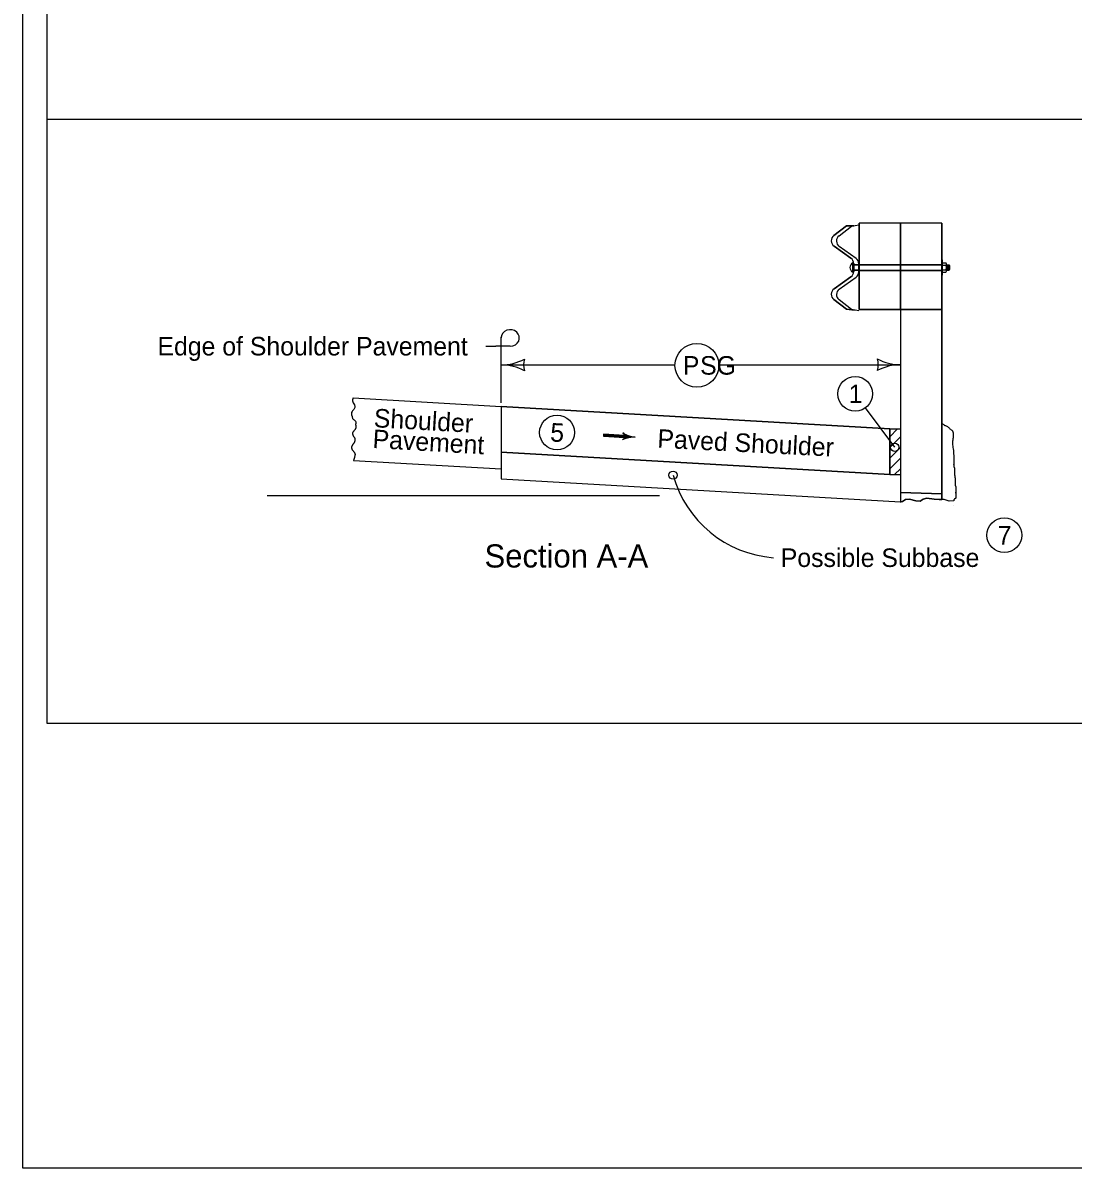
# Model space of a CAD drawing. Extents: x 6410 to 81668, y 3928 to 11667.
# Drawn here: x 10133 to 11038, y 7924 to 8912 of the extents above; entities that cross this region are included whole.
import ezdxf

# ---------------------------------------------------------------- set-up
doc = ezdxf.new("R2010")
doc.units = 0
for name, color, linetype in [('dsnCellElements', 7, 'Continuous'), ('dsnNonPlotable', 7, 'Continuous'), ('dsnShtPlotShapeBatchPrint', 7, 'Continuous'), ('dsnStdBlockModified', 7, 'Continuous'), ('Level 11', 7, 'Continuous'), ('Level 14', 7, 'Continuous'), ('Level 3', 7, 'Continuous'), ('Level 7', 7, 'Continuous'), ('Level 8', 7, 'Continuous')]:
    doc.layers.add(name, color=color, linetype=linetype)

msp = doc.modelspace()

# ---------------------------------------------------------------- linework, layer by layer
at = {"layer": 'dsnCellElements'}
for p, q in [((10545.11, 8620.44), (10545.11, 8641.3)), ((10531.74, 8633.28), (10540.43, 8633.28)), ((10552.92, 8633.28), (10540.43, 8633.28)), ((10545.11, 8584.5), (10545.11, 8620.44)), ((10651.5, 8555.4), (10633.29, 8556.45)), ((10651.39, 8554.46), (10651.39, 8554.46)), ((10651.51, 8556.4), (10651.51, 8556.4))]:
    msp.add_line(p, q, dxfattribs=at)
for points in [[(10651.52, 8556.34), (10633.36, 8557.39), (10633.23, 8555.51), (10651.39, 8554.46), (10651.45, 8556.07), (10633.58, 8557.16), (10633.52, 8555.67), (10651.01, 8554.72), (10651.13, 8555.84), (10633.81, 8556.9), (10633.79, 8555.9), (10650.8, 8554.92), (10650.89, 8555.62), (10634, 8556.68), (10633.98, 8556.12), (10650.59, 8555.18)], [(10651.12, 8557.59), (10651.81, 8556.43), (10651.79, 8554.78), (10651.03, 8553.38), (10653.79, 8554.25), (10656.98, 8554.9), (10657.88, 8555.03), (10655.64, 8555.58), (10652.41, 8556.81), (10651.47, 8557.34), (10651.59, 8553.83), (10656.54, 8555.05), (10651.9, 8556.63), (10651.91, 8554.21), (10655.31, 8555.14), (10652.31, 8556), (10652.08, 8554.62), (10654.24, 8555.12), (10652.65, 8555.63), (10652.51, 8554.97), (10653.3, 8555.13)]]:
    msp.add_lwpolyline(points, dxfattribs=at)
for centre, major_axis, start_param, end_param in [((10552.92, 8640.42), (-7.81, 0), 1.570796, 6.283185), ((10647.73, 8555.61), (3.88, 0), 5.202895, 7.237436), ((10662.79, 8575.03), (-22.17, 0), 0.954258, 1.478381), ((10660, 8534.61), (22.17, 0), 1.537172, 2.061295)]:
    msp.add_ellipse(centre, major_axis=major_axis, ratio=0.913811, start_param=start_param, end_param=end_param, dxfattribs=at)
at = {"layer": 'dsnNonPlotable'}
for p, q in [((10153.18, 9917.9), (10153.18, 8307.9)), ((10153.18, 8307.9), (13248.87, 8307.9))]:
    msp.add_line(p, q, dxfattribs=at)
at = {"layer": 'dsnShtPlotShapeBatchPrint'}
for p, q in [((10545.11, 8617.12), (10694.94, 8617.12)), ((10732.8, 8617.27), (10889.5, 8617.27))]:
    msp.add_line(p, q, dxfattribs=at)
msp.add_circle((10713.87, 8616.71), 18.93, dxfattribs=at)
for centre, radius, start, end in [((10545.11, 8659.62), 42.5, 270, 298.07249), ((10580.75, 8617.12), 16.42, 162.26665, 197.73335), ((10853.87, 8617.27), 16.42, 342.26665, 17.73335), ((10889.5, 8659.77), 42.5, 241.92751, 270), ((10545.11, 8574.62), 42.5, 61.92751, 90), ((10889.5, 8574.77), 42.5, 90, 118.07249), ((10787.43, 8548.23), 97.76, 195.59781, 265.55799)]:
    msp.add_arc(centre, radius, start, end, dxfattribs=at)
at = {"layer": 'dsnStdBlockModified'}
for p, q in [((10832.02, 8728.72), (10842.78, 8737.12)), ((10836.45, 8728.49), (10847.23, 8736.9)), ((10842.78, 8737.12), (10849.11, 8737.23)), ((10847.23, 8736.9), (10853.56, 8738.02)), ((10925.05, 8739.48), (10853.96, 8739.48)), ((10853.96, 8664.83), (10853.96, 8739.48)), ((10889.5, 8664.83), (10889.5, 8739.48)), ((10925.05, 8739.48), (10925.05, 8500.84)), ((10846.72, 8709.19), (10832.21, 8719.6)), ((10851.19, 8708.95), (10836.63, 8719.4)), ((10925.05, 8707.78), (10925.73, 8707.78)), ((10925.73, 8694.45), (10925.73, 8707.78)), ((10848.34, 8697.08), (10848.34, 8705.17)), ((10848.34, 8703.48), (10853.77, 8703.48)), ((10848.34, 8698.81), (10853.96, 8698.81)), ((10849.12, 8697.75), (10849.11, 8704.56)), ((10849.11, 8697.74), (10849.12, 8701.15)), ((10849.12, 8701.15), (10849.12, 8697.75)), ((10849.29, 8703.48), (10853.96, 8703.48)), ((10853.56, 8700.93), (10853.56, 8704.34)), ((10853.56, 8697.53), (10853.56, 8700.93)), ((10853.56, 8700.93), (10853.56, 8697.53)), ((10853.95, 8698.48), (10925.05, 8698.48)), ((10853.96, 8703.81), (10925.05, 8703.81)), ((10853.96, 8703.48), (10925.05, 8703.47)), ((10853.96, 8698.81), (10925.05, 8698.81)), ((10925.73, 8705.15), (10928.7, 8705.15)), ((10925.73, 8703.13), (10928.7, 8703.13)), ((10925.73, 8699.09), (10928.7, 8699.09)), ((10925.73, 8697.07), (10928.7, 8697.07)), ((10929.06, 8698.08), (10929.06, 8704.14)), ((10929.06, 8703.45), (10931.43, 8703.45)), ((10929.06, 8698.78), (10931.43, 8698.78)), ((10929.95, 8703.45), (10929.95, 8698.78)), ((10930.69, 8703.45), (10930.69, 8698.78)), ((10931.43, 8703.45), (10931.88, 8702.91)), ((10931.43, 8703.45), (10931.43, 8698.78)), ((10931.88, 8699.31), (10931.43, 8698.78)), ((10931.88, 8702.91), (10931.88, 8699.31)), ((10832.21, 8682.7), (10846.72, 8693.11)), ((10836.63, 8682.46), (10851.19, 8692.91)), ((10925.05, 8694.45), (10925.73, 8694.45)), ((10842.78, 8665.18), (10832.02, 8673.58)), ((10847.23, 8664.96), (10836.45, 8673.37)), ((10849.88, 8664.49), (10842.78, 8665.18)), ((10853.56, 8663.85), (10847.23, 8664.96)), ((10889.5, 8664.83), (10853.96, 8664.83)), ((10889.5, 8664.83), (10889.5, 8498.31)), ((10417.5, 8588.78), (10545.11, 8581.36)), ((10545.11, 8581.36), (10545.11, 8527.35)), ((10545.11, 8581.36), (10880.25, 8561.87)), ((10880.25, 8561.87), (10545.11, 8581.36)), ((10545.11, 8581.36), (10545.11, 8541.76)), ((10880.25, 8555.12), (10886.99, 8561.87)), ((10880.25, 8555.12), (10886.99, 8561.87)), ((10880.25, 8555.12), (10886.99, 8561.87)), ((10880.25, 8555.12), (10886.99, 8561.87)), ((10880.25, 8561.87), (10889.49, 8561.87)), ((10880.25, 8561.87), (10880.25, 8522.44)), ((10880.25, 8522.44), (10880.25, 8561.87)), ((10880.25, 8545.94), (10889.49, 8555.18)), ((10880.25, 8545.94), (10889.49, 8555.18)), ((10880.25, 8545.94), (10889.49, 8555.18)), ((10880.25, 8545.94), (10889.49, 8555.18)), ((10935.1, 8555.1), (10935.1, 8555.1)), ((10880.25, 8522.44), (10545.11, 8541.76)), ((10545.11, 8541.76), (10880.25, 8522.44)), ((10880.25, 8536.71), (10889.49, 8545.95)), ((10880.25, 8536.71), (10889.49, 8545.95)), ((10880.25, 8536.71), (10889.49, 8545.95)), ((10880.25, 8536.71), (10889.49, 8545.95)), ((10417.68, 8534.76), (10545.11, 8527.35)), ((10880.25, 8527.48), (10889.49, 8536.72)), ((10545.11, 8527.35), (10545.11, 8518.93)), ((10545.11, 8518.93), (10889.5, 8499.07)), ((10880.25, 8522.44), (10889.49, 8522.44)), ((10884.35, 8522.44), (10889.49, 8527.58)), ((10343.06, 8504.51), (10681.56, 8504.51)), ((10935.45, 8496.03), (10935.45, 8496.03))]:
    msp.add_line(p, q, dxfattribs=at)
for points in [[(10929.05, 8698.41), (10929, 8698.67), (10928.96, 8698.85), (10928.87, 8699), (10928.75, 8699.09), (10928.83, 8699.19), (10928.91, 8699.42), (10928.97, 8699.73), (10929.05, 8700.48), (10929.05, 8698.4), (10929.03, 8698.55), (10928.99, 8698.76), (10928.91, 8698.97), (10928.79, 8699.08), (10928.83, 8699.17), (10928.89, 8699.32), (10928.99, 8699.82), (10929.03, 8700.2), (10929.03, 8698.6), (10929, 8698.72), (10928.96, 8698.88), (10928.83, 8699.08), (10928.88, 8699.25), (10928.96, 8699.59), (10929.02, 8699.91), (10929.01, 8698.75), (10928.97, 8698.88), (10928.86, 8699.07), (10928.9, 8699.29), (10928.96, 8699.55), (10928.99, 8699.72), (10928.99, 8698.86), (10928.93, 8698.96), (10928.88, 8699.08), (10928.97, 8699.54), (10928.97, 8698.94), (10928.9, 8699.07), (10928.95, 8699.37), (10928.95, 8699.01), (10928.92, 8699.08), (10928.93, 8699.18), (10928.93, 8699.11)], [(10928.76, 8703.14), (10928.83, 8703.18), (10928.91, 8703.28), (10928.99, 8703.5), (10929.05, 8703.79), (10929.05, 8701.84), (10928.99, 8702.36), (10928.94, 8702.73), (10928.82, 8703.05), (10928.76, 8703.13), (10928.82, 8703.14), (10928.92, 8703.29), (10929.01, 8703.52), (10929.03, 8703.67), (10929.03, 8702.13), (10928.96, 8702.63), (10928.9, 8702.89), (10928.8, 8703.11), (10928.83, 8703.13), (10928.97, 8703.34), (10929.01, 8703.5), (10929.01, 8702.39), (10928.82, 8703.1), (10928.99, 8703.38), (10928.99, 8702.53), (10928.85, 8703.09), (10928.97, 8703.31), (10928.98, 8702.67), (10928.87, 8703.07), (10928.96, 8703.25), (10928.96, 8702.83), (10928.89, 8703.06), (10928.94, 8703.17), (10928.94, 8702.97), (10928.91, 8703.04), (10928.92, 8703.09)], [(10935.57, 8531.26), (10935.51, 8530.99), (10935.51, 8530.79), (10935.51, 8530.6), (10935.51, 8530.4), (10935.51, 8530.21), (10935.51, 8530.01), (10935.51, 8529.72), (10935.51, 8529.52), (10935.61, 8529.23), (10935.71, 8528.94), (10935.9, 8528.74), (10935.9, 8528.55), (10936, 8528.35), (10936, 8528.16), (10936, 8527.96), (10936.1, 8527.86), (10936.1, 8527.67), (10936.1, 8527.47), (10936.1, 8527.28), (10936.1, 8527.08), (10936.1, 8526.89), (10936.1, 8526.59), (10936.1, 8526.3), (10936.1, 8526.1), (10936.1, 8525.81), (10936.1, 8525.62), (10936.1, 8525.42), (10936.2, 8525.32), (10936.2, 8525.13), (10936.2, 8524.93), (10936.2, 8524.74), (10936.2, 8524.54), (10936.2, 8524.34), (10936.2, 8524.15), (10936.2, 8523.95), (10936.2, 8523.76), (10936.2, 8523.56), (10936.2, 8523.37), (10936.2, 8523.17), (10936.2, 8522.98), (10936.2, 8522.78), (10936.2, 8522.59), (10936.2, 8522.39), (10936.2, 8522.2), (10936.2, 8522), (10936.2, 8521.8), (10936.29, 8521.71), (10936.29, 8521.51), (10936.29, 8521.32), (10936.39, 8521.22), (10936.39, 8521.02), (10936.39, 8520.83), (10936.49, 8520.73), (10936.49, 8520.53), (10936.49, 8520.34), (10936.49, 8520.14), (10936.49, 8519.85), (10936.59, 8519.56), (10936.59, 8519.36), (10936.59, 8519.17), (10936.59, 8518.97), (10936.59, 8518.78), (10936.59, 8518.58), (10936.59, 8518.38), (10936.59, 8518.19), (10936.59, 8517.99), (10936.59, 8517.8), (10936.59, 8517.6), (10936.59, 8517.41), (10936.59, 8517.21), (10936.59, 8517.02), (10936.59, 8516.82), (10936.59, 8516.63), (10936.59, 8516.43), (10936.59, 8516.24), (10936.59, 8516.04), (10936.59, 8515.84), (10936.59, 8515.65), (10936.59, 8515.45), (10936.59, 8515.26), (10936.59, 8515.06), (10936.59, 8514.87), (10936.59, 8514.67), (10936.59, 8514.48), (10936.59, 8514.28), (10936.59, 8514.09), (10936.59, 8513.89), (10936.68, 8513.79), (10936.68, 8513.5), (10936.68, 8513.3), (10936.78, 8513.11), (10936.88, 8512.82), (10936.88, 8512.62), (10936.98, 8512.52), (10936.98, 8512.33), (10937.07, 8512.23), (10937.17, 8512.13), (10937.17, 8511.94), (10937.17, 8511.74), (10937.17, 8511.55), (10937.27, 8511.45), (10937.27, 8511.25), (10937.27, 8511.06), (10937.27, 8510.86), (10937.27, 8510.67), (10937.27, 8510.47), (10937.27, 8510.28), (10937.27, 8510.08), (10937.27, 8509.88), (10937.27, 8509.69), (10937.27, 8509.49), (10937.27, 8509.3), (10937.27, 8509.1), (10937.27, 8508.91), (10937.27, 8508.71), (10937.27, 8508.52), (10937.27, 8508.32), (10937.27, 8508.13), (10937.27, 8507.93), (10937.27, 8507.74), (10937.27, 8507.54), (10937.27, 8507.34), (10937.27, 8507.15), (10937.27, 8506.95), (10937.27, 8506.76), (10937.27, 8506.56), (10937.27, 8506.56), (10937.27, 8506.86), (10937.27, 8507.05), (10937.27, 8507.25), (10937.27, 8507.05), (10937.27, 8506.86), (10937.27, 8506.66), (10937.27, 8506.46), (10937.27, 8506.27), (10937.27, 8506.07), (10937.27, 8505.88), (10937.27, 8505.68), (10937.27, 8505.49), (10937.27, 8505.29), (10937.27, 8505.1), (10937.27, 8504.9), (10937.27, 8504.71), (10937.27, 8504.51), (10937.27, 8504.32), (10937.17, 8504.22), (10937.17, 8504.02), (10937.17, 8503.83), (10937.17, 8503.63), (10937.17, 8503.44), (10937.17, 8503.24), (10937.17, 8503.05), (10937.17, 8502.85), (10937.17, 8502.65), (10937.17, 8502.46), (10937.17, 8502.26), (10937.07, 8502.17), (10936.98, 8501.97), (10936.88, 8501.87), (10936.78, 8501.78), (10936.68, 8501.68), (10936.49, 8501.58), (10936.29, 8501.58), (10936.2, 8501.48), (10936.1, 8501.38), (10936, 8501.29), (10935.8, 8501.19), (10935.71, 8501.09), (10935.71, 8500.9), (10935.61, 8500.8), (10935.61, 8500.6), (10935.61, 8500.41), (10935.61, 8500.21), (10935.61, 8500.02), (10935.61, 8499.92), (10935.61, 8500.11)], [(10935.57, 8499.8), (10931.42, 8499.68), (10927.28, 8500.84), (10922.73, 8500.84), (10918.49, 8501.27), (10912.23, 8502.01), (10909.16, 8501.37), (10906.51, 8499.57), (10902.8, 8499.78), (10897.18, 8501.37), (10893.9, 8500.84), (10891.14, 8499.25), (10889.5, 8499.03)]]:
    msp.add_lwpolyline(points, dxfattribs=at)
msp.add_circle((10593.23, 8558.79), 15, dxfattribs=at)
for centre, radius, start, end in [((10835.49, 8724.23), 5.68, 127.75002, 234.69086), ((10839.94, 8724.02), 5.68, 127.75002, 234.69086), ((10843.44, 8704.56), 5.68, 360, 54.69099), ((10847.88, 8704.34), 5.68, 360, 54.69099), ((10850.42, 8701.13), 4.54, 117.20289, 242.8461), ((10843.44, 8697.74), 5.68, 305.30901, 0), ((10847.88, 8697.53), 5.68, 305.30901, 0), ((10835.49, 8678.07), 5.68, 125.30914, 232.24998), ((10839.94, 8677.85), 5.68, 125.30914, 232.24998)]:
    msp.add_arc(centre, radius, start, end, dxfattribs=at)
for centre in [(10928.7, 8704.14), (10928.7, 8698.08)]:
    msp.add_ellipse(centre, major_axis=(0, -1.01), ratio=0.362258, start_param=6.283156, end_param=9.424748, dxfattribs=at)
for points in [[(10417.5, 8588.78), (10416.99, 8585.18), (10418.03, 8583.67), (10418.9, 8581.37), (10418.29, 8579.31), (10416.39, 8576.94), (10415.87, 8575.04), (10416.39, 8572.74), (10417.25, 8570.37), (10418.29, 8569.65), (10419.68, 8567.12), (10419.67, 8566.28)], [(10417.71, 8549.17), (10417.92, 8549.41), (10418.12, 8549.68), (10418.47, 8550.23), (10418.75, 8550.83), (10418.87, 8551.13), (10418.97, 8551.45), (10419.1, 8552.07), (10419.15, 8552.69), (10419.1, 8553.27), (10419.04, 8553.55), (10419, 8553.69), (10418.96, 8553.82), (10418.75, 8554.19), (10418.47, 8554.56), (10418.17, 8554.92), (10417.92, 8555.32), (10417.78, 8555.61), (10417.64, 8555.89), (10417.38, 8556.46), (10417.18, 8557.03), (10417.1, 8557.32), (10417.05, 8557.62), (10417.04, 8557.75), (10417.04, 8557.87), (10417.19, 8558.65), (10417.4, 8559.17), (10417.66, 8559.68), (10418.1, 8560.32), (10418.62, 8560.86), (10419.13, 8561.41), (10419.37, 8561.71), (10419.56, 8562.05), (10419.77, 8562.53), (10419.93, 8563), (10420.03, 8563.48), (10420.06, 8563.72), (10420.08, 8563.84), (10420.08, 8563.95), (10420.04, 8564.46), (10419.89, 8564.98), (10419.84, 8565.1), (10419.78, 8565.23), (10419.73, 8565.36), (10419.71, 8565.49), (10419.67, 8566.28)], [(10935.57, 8531.26), (10935.89, 8534.17), (10935.67, 8539.03), (10935.23, 8544.78), (10934.56, 8549.2), (10934.78, 8552.52), (10935.23, 8556.72), (10934.56, 8559.82), (10932.35, 8561.81), (10930.36, 8563.58), (10928.15, 8564.68), (10925.94, 8566.01), (10925.06, 8566.67)], [(10417.71, 8549.17), (10417.49, 8548.93), (10417.25, 8548.7), (10417.01, 8548.45), (10416.83, 8548.19), (10416.69, 8547.9), (10416.55, 8547.62), (10416.29, 8547.05), (10416.18, 8546.76), (10416.08, 8546.48), (10416.01, 8546.18), (10415.98, 8546.04), (10415.96, 8545.89), (10415.97, 8545.37), (10416.1, 8544.86), (10416.31, 8544.34), (10416.57, 8543.83), (10417.01, 8543.19), (10417.53, 8542.65), (10418.05, 8542.1), (10418.28, 8541.8), (10418.48, 8541.46), (10418.88, 8540.51), (10418.99, 8540.03), (10419, 8539.55), (10418.96, 8539.27), (10418.91, 8538.98), (10418.86, 8538.69), (10418.79, 8538.41), (10418.48, 8537.26), (10418.3, 8536.65), (10418.1, 8536.05), (10417.88, 8535.46), (10417.75, 8535.17), (10417.61, 8534.88), (10417.53, 8534.77)]]:
    msp.add_spline(points, degree=3, dxfattribs=at)
at = {"layer": 'Level 11'}
for p, q in [((12308.76, 8828.9), (10153.18, 8828.9)), ((10884.57, 8546.04), (10859.18, 8579.97))]:
    msp.add_line(p, q, dxfattribs=at)
at = {"layer": 'Level 14'}
msp.add_circle((10693.27, 8521.95), 3.54, dxfattribs=at)
at = {"layer": 'Level 3'}
for p, q in [((10832.21, 8719.6), (10846.72, 8709.19)), ((10846.72, 8693.11), (10832.21, 8682.7))]:
    msp.add_line(p, q, dxfattribs=at)
for points in [[(10836.46, 8728.5), (10836.45, 8728.49), (10847.23, 8736.9), (10849.11, 8737.23), (10842.78, 8737.12), (10832.02, 8728.72)], [(10889.5, 8703.81), (10889.5, 8739.48), (10853.96, 8739.48), (10853.96, 8703.81), (10853.96, 8703.81), (10889.5, 8703.81)], [(10925.05, 8703.81), (10925.05, 8707.81), (10925.05, 8739.48), (10889.5, 8739.48), (10889.5, 8703.81), (10925.05, 8703.81)], [(10851.17, 8708.97), (10851.19, 8708.95), (10836.63, 8719.4), (10836.66, 8719.38)], [(10849.11, 8704.56), (10849.11, 8703.48), (10853.56, 8703.48), (10853.56, 8704.34), (10853.56, 8704.34)], [(10853.56, 8697.53), (10853.56, 8697.53), (10853.56, 8698.81), (10849.12, 8698.81), (10849.12, 8697.75), (10849.12, 8698.81), (10849.11, 8698.81), (10849.11, 8697.74)], [(10853.96, 8703.48), (10853.96, 8698.81), (10853.96, 8698.81), (10889.5, 8698.81), (10889.5, 8703.48), (10853.96, 8703.48), (10853.96, 8703.48)], [(10853.96, 8698.48), (10853.96, 8664.83), (10889.5, 8664.83), (10889.5, 8698.48), (10853.96, 8698.48)], [(10925.05, 8698.81), (10925.05, 8703.47), (10889.5, 8703.48), (10889.5, 8698.81), (10925.05, 8698.81)], [(10925.05, 8664.83), (10925.05, 8694.48), (10925.05, 8698.48), (10889.5, 8698.48), (10889.5, 8664.83), (10925.05, 8664.83)], [(10836.66, 8682.48), (10836.63, 8682.46), (10851.19, 8692.91), (10851.17, 8692.89)], [(10832.02, 8673.58), (10842.78, 8665.18), (10849.88, 8664.49), (10847.23, 8664.96), (10836.45, 8673.37), (10836.46, 8673.36)], [(10925.05, 8505.89), (10925.05, 8664.83), (10889.5, 8664.83), (10889.5, 8561.87), (10889.5, 8555.18), (10889.5, 8555.18), (10889.5, 8555.18), (10889.5, 8545.95), (10889.5, 8545.95), (10889.5, 8545.95), (10889.5, 8536.81), (10889.5, 8536.81), (10889.5, 8536.81), (10889.5, 8529.88), (10889.5, 8507.05), (10925.05, 8505.89)], [(10925.05, 8505.89), (10889.5, 8507.05), (10889.5, 8499.03), (10891.14, 8499.25), (10893.9, 8500.84), (10897.18, 8501.37), (10902.8, 8499.78), (10906.51, 8499.57), (10909.16, 8501.37), (10912.23, 8502.01), (10918.49, 8501.27), (10922.73, 8500.84), (10925.05, 8500.84), (10925.05, 8505.89)]]:
    msp.add_lwpolyline(points, dxfattribs=at)
msp.add_lwpolyline([(10853.56, 8703.48), (10849.11, 8703.48), (10849.12, 8700.02), (10849.12, 8701.15), (10849.12, 8698.81), (10853.56, 8698.81)], close=True, dxfattribs=at)
for centre, start, end in [((10835.49, 8724.23), 127.75002, 234.69086), ((10839.94, 8724.02), 127.75002, 234.69086), ((10843.44, 8704.56), 0, 54.69099), ((10847.88, 8704.34), 0, 54.69099), ((10843.44, 8697.74), 305.30901, 0), ((10847.88, 8697.53), 305.30901, 0), ((10835.49, 8678.07), 125.30914, 232.24998), ((10839.94, 8677.85), 125.30914, 232.24998)]:
    msp.add_arc(centre, 5.68, start, end, dxfattribs=at)
at = {"layer": 'Level 7'}
for centre, radius in [((10850.44, 8592.16), 15), ((10593.23, 8558.79), 15), ((10884.57, 8546.04), 3.58), ((10979.03, 8470.14), 15)]:
    msp.add_circle(centre, radius, dxfattribs=at)
at = {"layer": 'Level 8'}
msp.add_lwpolyline([(10132.52, 9944.02), (13267.53, 9944.02), (13267.53, 7924.02), (10132.52, 7924.02)], close=True, dxfattribs=at)

# ---------------------------------------------------------------- texts
at = {"layer": 'dsnCellElements'}
for s, height, p in [('Edge of Shoulder Pavement', 16, (10248.58, 8625.28)), ('Section A-A', 20, (10530.69, 8442.27)), ('Possible Subbase', 16, (10786.21, 8442.76))]:
    msp.add_text(s, height=height, dxfattribs=at).set_placement(p)
for s, rotation, p in [('Shoulder', 356.73462, (10434.87, 8563.43)), ('Pavement', 356.73462, (10433.84, 8545.46)), ('Paved Shoulder ', 357.0678, (10679.51, 8545.76))]:
    msp.add_text(s, height=16, rotation=rotation, dxfattribs=at).set_placement(p)
at = {"layer": 'dsnShtPlotShapeBatchPrint'}
for s, p in [('P', (10701.74, 8608.71)), ('SG', (10716.66, 8608.71))]:
    msp.add_text(s, height=16, dxfattribs=at).set_placement(p)
at = {"layer": 'Level 7'}
for s, p in [('1', (10844.82, 8584.16)), ('7', (10973.32, 8462.14))]:
    msp.add_text(s, height=16, dxfattribs=at).set_placement(p)
msp.add_text('5', height=16, rotation=356.69973, dxfattribs=at).set_placement((10587.01, 8551.13))

doc.saveas('drawing.dxf')
